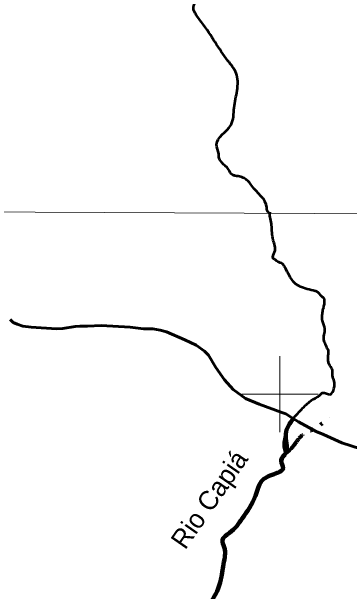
# Model space of a CAD drawing. Extents: x 553962 to 842807, y 8883888 to 9032388.
# Drawn here: x 667950 to 676824, y 8994810 to 9010061 of the extents above; entities that cross this region are included whole.
import ezdxf
from ezdxf.enums import TextEntityAlignment as Align

# ---------------------------------------------------------------- set-up
doc = ezdxf.new("R2010")
doc.units = 0
doc.header["$LTSCALE"] = 200
doc.linetypes.add('DASH_DOUBLE_DOT', pattern=[9.2, 5, -1.2, 0.3, -1.2, 0.3, -1.2])
doc.linetypes.add('LONG_DASH_SHORT_DASH', pattern=[9.9, 6, -1.2, 1.5, -1.2])
for name, color, linetype, lineweight in [('1', 7, 'Continuous', 13), ('11', 7, 'DASH_DOUBLE_DOT', 106), ('2', 7, 'Continuous', 13), ('24', 7, 'Continuous', 25), ('7', 7, 'LONG_DASH_SHORT_DASH', 60), ('9', 7, 'Continuous', 90)]:
    doc.layers.add(name, color=color, linetype=linetype, lineweight=lineweight)
doc.layers.add('49', color=7, linetype='Continuous')

msp = doc.modelspace()

# ---------------------------------------------------------------- linework, layer by layer
at = {"layer": '1'}
msp.add_lwpolyline([(565303.2, 9005146.6), (664889.8, 9004806.7), (719872.1, 9004543.9), (790635.8, 9004109)], dxfattribs=at)
at = {"layer": '11'}
for points in [[(673192.8, 8986819.2), (673266.9, 8987063), (672967.2, 8987378.4), (672888.4, 8987819.9), (673046.1, 8988482.3), (673345.7, 8989160.4), (673503.4, 8989586.2), (673377.3, 8989901.6), (673046.1, 8990153.9), (673014.5, 8990469.3), (673109.2, 8990705.9), (673156.5, 8990942.4), (672983, 8991115.9), (672793.8, 8991510.2), (672841.1, 8992330.2), (672841.1, 8992787.6), (672809.5, 8993118.7), (672683.4, 8993386.8), (672809.5, 8993733.8), (673077.6, 8994335.6), (673377.3, 8994887.9), (673519.2, 8995534.8), (673535, 8995976.6), (673487.7, 8996159.6), (673676.9, 8996349), (674008.1, 8996727.7), (674355, 8997327.2), (674512.7, 8997705.9), (674843.9, 8997895.2), (675080.4, 8998053), (675033.1, 8998242.4), (675269.7, 8998542.2), (675569.3, 8998905.1), (675963.6, 8999126), (676294.7, 8999394.2)], [(673192.8, 8986819.2), (673266.9, 8987063), (672967.2, 8987378.4), (672888.4, 8987819.9), (673046.1, 8988482.3), (673345.7, 8989160.4), (673503.4, 8989586.2), (673377.3, 8989901.6), (673046.1, 8990153.9), (673014.5, 8990469.3), (673109.2, 8990705.9), (673156.5, 8990942.4), (672983, 8991115.9), (672793.8, 8991510.2), (672841.1, 8992330.2), (672841.1, 8992787.6), (672809.5, 8993118.7), (672683.4, 8993386.8), (672809.5, 8993733.8), (673077.6, 8994335.6), (673377.3, 8994887.9), (673519.2, 8995534.8), (673535, 8995976.6), (673487.7, 8996159.6), (673676.9, 8996349), (674008.1, 8996727.7), (674355, 8997327.2), (674512.7, 8997705.9), (674843.9, 8997895.2), (675080.4, 8998053), (675033.1, 8998242.4), (675269.7, 8998542.2), (675569.3, 8998905.1), (675861.5, 8999064.7)]]:
    msp.add_spline(points, degree=3, dxfattribs=at)
at = {"layer": '2'}
for p, q in [((675000, 8999000), (675000, 9001000)), ((674000, 9000000), (676000, 9000000))]:
    msp.add_line(p, q, dxfattribs=at)
at = {"layer": '24', "lineweight": 53}
for points in [[(674726.7, 9004751), (674666.6, 9004817.9), (674653.2, 9004904.8), (674258.7, 9005480.2), (674171.8, 9005593.9), (674084.9, 9005660.8), (673971.2, 9005714.3), (673824.1, 9005741.1), (673750.6, 9005767.8), (673650.3, 9005908.3), (673469.7, 9006089), (673396.2, 9006242.8), (673389.5, 9006323.1), (673336, 9006563.9), (673714.2, 9007080), (673794.5, 9007534.9), (673874.7, 9007989.8), (673848, 9008444.8), (673634, 9008765.9), (672938.7, 9009782.8), (672724.7, 9010157.4), (673339.8, 9010746.1), (673527, 9010906.7), (673874.7, 9011040.5), (674008.4, 9011227.8), (673874.7, 9011896.8), (673981.7, 9012137.6), (674115.4, 9012271.4), (674222.4, 9012699.6), (673848, 9012699.6), (673500.3, 9012967.2), (672751.4, 9012886.9), (672564.2, 9013208), (672377, 9013341.8), (672243.3, 9013796.7), (672109.6, 9013957.3), (671868.9, 9014171.4), (671869.6, 9014455.6), (671949.9, 9014696.4), (672110.3, 9015231.6), (672244.1, 9015633), (672190.6, 9015820.4), (671869.6, 9015847.1), (671762.7, 9016088), (671495.2, 9016248.5), (671441.7, 9016596.4), (671094.1, 9016623.2), (670505.7, 9016837.2), (670211.5, 9016971), (670024.3, 9017265.4)], [(675154.1, 8998412.8), (675100.6, 8998680.4), (675187.5, 8999035), (675307.8, 8999295.9), (675575.3, 8999603.6), (675822.7, 8999831.1), (676043.3, 8999971.6), (676116.8, 9000031.8), (676324.1, 8999991.6), (676417.7, 9000145.5), (676424.4, 9000339.5), (676377.6, 9000486.7), (676377.6, 9000627.2), (676357.6, 9000680.7), (676277.3, 9000827.9), (676264, 9000914.9), (676270.6, 9001048.7), (676277.3, 9001122.2), (676243.9, 9001202.5), (676183.7, 9001339.3), (676157, 9001392.8), (676163.7, 9001566.7), (676177, 9001713.9), (676116.8, 9001928), (676110.2, 9002075.2), (676130.2, 9002209), (676163.7, 9002342.8), (676170.3, 9002389.6), (676150.3, 9002523.4), (676116.8, 9002550.2), (675949.7, 9002704), (675923, 9002710.7), (675515.1, 9002833.7), (675475, 9002853.7), (675113.9, 9003362.2), (675067.1, 9003422.4), (674940.1, 9003482.6), (674859.8, 9003542.8), (674819.7, 9003569.6), (674859.8, 9003736.8), (674819.7, 9004051.2), (674779.6, 9004439.2), (674752.9, 9004606.5), (674739.5, 9004773.7), (674742.2, 9004781.9)], [(673192.8, 8986819.2), (673266.9, 8987063), (672967.2, 8987378.4), (672888.4, 8987819.9), (673046.1, 8988482.3), (673345.7, 8989160.4), (673503.4, 8989586.2), (673377.3, 8989901.6), (673046.1, 8990153.9), (673014.5, 8990469.3), (673109.2, 8990705.9), (673156.5, 8990942.4), (672983, 8991115.9), (672793.8, 8991510.2), (672841.1, 8992330.2), (672841.1, 8992787.6), (672809.5, 8993118.7), (672683.4, 8993386.8), (672809.5, 8993733.8), (673077.6, 8994335.6), (673377.3, 8994887.9), (673519.2, 8995534.8), (673535, 8995976.6), (673487.7, 8996159.6), (673676.9, 8996349), (674008.1, 8996727.7), (674355, 8997327.2), (674512.7, 8997705.9), (674843.9, 8997895.2), (675080.4, 8998053), (675033.1, 8998242.4), (675144.3, 8998385.5)]]:
    msp.add_spline(points, degree=3, dxfattribs=at)
at = {"layer": '7'}
msp.add_lwpolyline([(667913.5, 9001963.7), (667993.5, 9001885.6), (668093.1, 9001836.3), (668244.3, 9001789.9), (668460.2, 9001759), (669127.8, 9001717.8), (669295.7, 9001729.2), (669615.5, 9001778.1), (669741.5, 9001789.9), (669941.5, 9001784.9), (670299.8, 9001804.4), (671060.9, 9001759.2), (671415.5, 9001717.4), (671657.5, 9001718.6), (671854, 9001684.6), (672015, 9001638.1), (672500.4, 9001430.7), (672799.2, 9001283), (673014.1, 9001129.5), (673119.7, 9001025.4), (673313.7, 9000701.2), (673543.2, 9000376.6), (673773.3, 9000119.8), (674094, 8999888.1), (674450.8, 8999736.6), (675045.9, 8999515.4), (675152, 8999479), (675299.7, 8999387.4), (675485.8, 8999269.7), (675948.3, 8999017.4), (676147.6, 8998938.2), (676626.5, 8998721.2), (677112.3, 8998555.8)], dxfattribs=at)
at = {"layer": '9'}
msp.add_spline([(673192.8, 8986819.2), (673266.9, 8987063), (672967.2, 8987378.4), (672888.4, 8987819.9), (673046.1, 8988482.3), (673345.7, 8989160.4), (673503.4, 8989586.2), (673377.3, 8989901.6), (673046.1, 8990153.9), (673014.5, 8990469.3), (673109.2, 8990705.9), (673156.5, 8990942.4), (672983, 8991115.9), (672793.8, 8991510.2), (672841.1, 8992330.2), (672841.1, 8992787.6), (672809.5, 8993118.7), (672683.4, 8993386.8), (672809.5, 8993733.8), (673077.6, 8994335.6), (673377.3, 8994887.9), (673519.2, 8995534.8), (673535, 8995976.6), (673487.7, 8996159.6), (673676.9, 8996349), (674008.1, 8996727.7), (674355, 8997327.2), (674512.7, 8997705.9), (674843.9, 8997895.2), (675080.4, 8998053), (675033.1, 8998242.4), (675150.3, 8998458.4), (675150.3, 8998951.2), (675361.3, 8999361.8)], degree=3, dxfattribs=at)

# ---------------------------------------------------------------- texts
at = {"layer": '49'}
msp.add_text('Rio Capiá', height=500, rotation=55.175, dxfattribs=at).set_placement((673347.5, 8997088.6), align=Align.CENTER)

doc.saveas('drawing.dxf')
